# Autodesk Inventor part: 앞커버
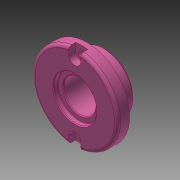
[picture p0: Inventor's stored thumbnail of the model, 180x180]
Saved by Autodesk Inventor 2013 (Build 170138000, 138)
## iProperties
Created: 2022-03
Part Number: 앞커버
Material: Generic
Document SubType Name: Modeling
Designer: mdu-01
Density: 1 g/cm^3
Author: mdu-01
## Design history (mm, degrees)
sketch "스케치1"
  geometry: L1 (0, 0)-(0, -20); L2 (14, 0)-(28, 0); L3 (28, 0)-(28, -8); L4 (28, -8)-(19, -8); L5 (19, -8)-(19, -20); L6 (19, -20)-(10.5, -20); L7 (14, 0)-(14, -3); L8 (14, -3)-(10.5, -3); L9 (10.5, -3)-(10.5, -20)
  constraints: 18 end point, 5 perpendicular, 2 horizontal alignment, 2 parallel, 1 horizontal, 1 vertical
  dimensions: "d0" = 56 diameter of L3 L1; "d2" = 38 diameter of L5 L1; "d3" = 8 distance of L2.end L3.end; "d4" = 20 distance between parallel lines of L2 L6; "d5" = 21 diameter of L9 L1; "d6" = 28 diameter of L7 L1; "d7" = 3 distance of L2.start L7.end
revolve "회전1" sketch "스케치1" stored, may be unused: angle "d8" = 90 deg
fillet "모깎기1" dims "d9" = 0.5
chamfer "모따기1" distance "d10" = 0.5; stored, may be unused: second distance "d11" = 2, angle "d12" = 45 deg
chamfer "모따기2" distance "d13" = 1; stored, may be unused: second distance "d14" = 2, angle "d15" = 45 deg
fillet "모깎기2" dims "d32" = 2
sketch "스케치2" dims "d16" = 46
  geometry: 3 further points
  constraints: 2 vertical alignment, 1 coincident, 2 other
hole "구멍1" sketch "스케치2" at (0, 23) diameter "d18" = 4.5; stored, may be unused: countersink angle "d22" = 90 deg, drill point angle "d24" = 118 deg; dims "d19" = 6, "d20" = 8, "d21" = 4.6, "d23" = 8
sketch "스케치3"
  geometry: L1 (4, 23)-(4, 27.713); L2 (-4, 23)-(-4, 27.713); A1 r 4 centre (0, 23) between (-4, 23) and (4, 23) reference; A2 r 28 centre (0, 0) between (4, 27.713) and (-4, 27.713) reference; 1 further point
  constraints: 4 end point, 4 point on circle, 2 tangent, 1 parallel, 1 vertical
extrude "돌출1" cut sketch "스케치3" stored distance "d27" = 10; taper "d28" = 0 deg
fillet "모깎기3" dims "d33" = 0.3
node "솔리드1"
pattern_circular "원형 패턴1" dims angle "d30" = 360 deg
